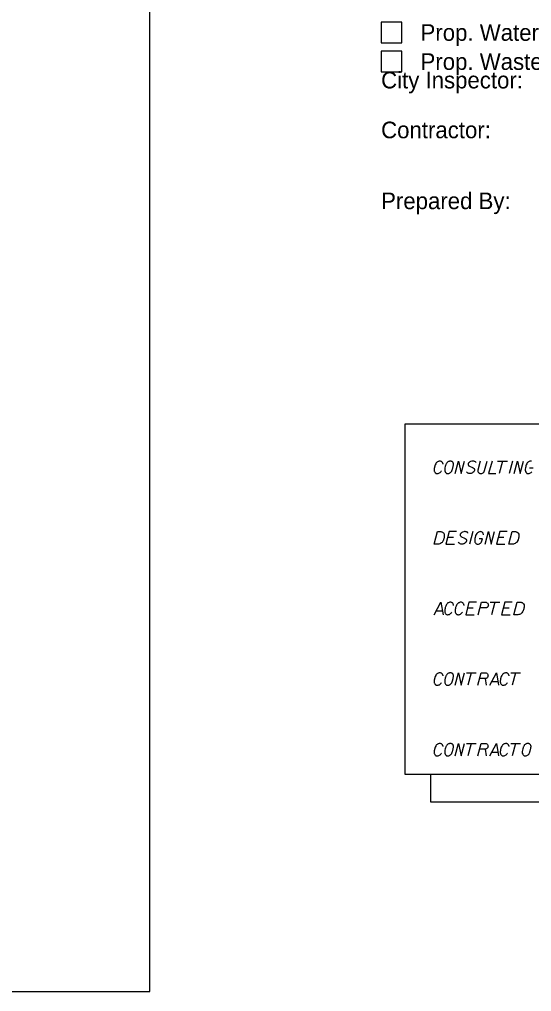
# Model space of a CAD drawing. Extents: x -2178 to -1318, y -1569 to -1077.
# Drawn here: x -1473.9 to -1412.2, y -1562.4 to -1445.4 of the extents above; entities that cross this region are included whole.
import ezdxf

# ---------------------------------------------------------------- set-up
doc = ezdxf.new("R2010")
doc.units = 0
for name, color, linetype in [('G_BORDER', 7, 'Continuous'), ('G_SHEET_EDGE', 7, 'Continuous'), ('G_SIGNATURE BLOCK', 7, 'Continuous')]:
    doc.layers.add(name, color=color, linetype=linetype)

msp = doc.modelspace()

# ---------------------------------------------------------------- linework, layer by layer
at = {"layer": 'G_BORDER'}
for points in [[(-1427.4, -1494.09), (-1321.4, -1494.09), (-1321.4, -1536.31), (-1427.4, -1536.31)], [(-1427.4, -1494.09), (-1321.4, -1494.09), (-1321.4, -1536.31), (-1427.4, -1536.31)], [(-1318.34, -1496.91), (-1321.4, -1496.91), (-1321.4, -1536.31), (-1424.34, -1536.31), (-1424.34, -1539.6), (-1318.34, -1539.6)]]:
    msp.add_lwpolyline(points, close=True, dxfattribs=at)
for points in [[(-1422.84, -1498.94), (-1422.84, -1498.9), (-1422.85, -1498.86), (-1422.86, -1498.81), (-1422.89, -1498.76), (-1422.9, -1498.74), (-1422.93, -1498.69), (-1422.97, -1498.65), (-1423.02, -1498.62), (-1423.06, -1498.6), (-1423.13, -1498.57), (-1423.19, -1498.56), (-1423.22, -1498.56), (-1423.29, -1498.57), (-1423.37, -1498.6), (-1423.43, -1498.62), (-1423.5, -1498.65), (-1423.56, -1498.69), (-1423.62, -1498.74), (-1423.65, -1498.78), (-1423.69, -1498.84), (-1423.72, -1498.9), (-1423.78, -1499.02), (-1423.82, -1499.13), (-1423.84, -1499.21), (-1423.85, -1499.26), (-1423.87, -1499.32), (-1423.89, -1499.45), (-1423.9, -1499.54), (-1423.9, -1499.65), (-1423.89, -1499.76), (-1423.87, -1499.82), (-1423.83, -1499.88), (-1423.81, -1499.92), (-1423.76, -1499.98), (-1423.69, -1500.04), (-1423.64, -1500.05), (-1423.57, -1500.06), (-1423.52, -1500.06), (-1423.51, -1500.06), (-1423.43, -1500.05), (-1423.34, -1500.02), (-1423.28, -1499.99), (-1423.19, -1499.93), (-1423.12, -1499.86), (-1423.06, -1499.79), (-1423.04, -1499.74)], [(-1421.93, -1498.56), (-1421.95, -1498.56), (-1422.02, -1498.57), (-1422.07, -1498.58), (-1422.11, -1498.6), (-1422.17, -1498.62), (-1422.24, -1498.65), (-1422.3, -1498.69), (-1422.35, -1498.74), (-1422.39, -1498.78), (-1422.43, -1498.84), (-1422.46, -1498.9), (-1422.5, -1498.97), (-1422.52, -1499.02), (-1422.54, -1499.09), (-1422.58, -1499.21), (-1422.61, -1499.39), (-1422.64, -1499.53), (-1422.64, -1499.66), (-1422.63, -1499.75), (-1422.58, -1499.86), (-1422.54, -1499.92), (-1422.48, -1499.99), (-1422.41, -1500.04), (-1422.38, -1500.05), (-1422.31, -1500.06), (-1422.25, -1500.06), (-1422.15, -1500.05), (-1422.07, -1500.02), (-1422.01, -1499.99), (-1421.93, -1499.93), (-1421.89, -1499.89), (-1421.85, -1499.85), (-1421.81, -1499.8), (-1421.79, -1499.76), (-1421.76, -1499.71), (-1421.75, -1499.68), (-1421.73, -1499.62), (-1421.71, -1499.55), (-1421.68, -1499.48), (-1421.67, -1499.43), (-1421.66, -1499.4), (-1421.65, -1499.35), (-1421.62, -1499.25), (-1421.61, -1499.19), (-1421.6, -1499.13), (-1421.59, -1499.04), (-1421.58, -1498.94), (-1421.58, -1498.9), (-1421.59, -1498.86), (-1421.6, -1498.81), (-1421.63, -1498.74), (-1421.67, -1498.69), (-1421.71, -1498.65), (-1421.75, -1498.62), (-1421.8, -1498.6), (-1421.84, -1498.58), (-1421.87, -1498.57), (-1421.93, -1498.56)], [(-1421.37, -1500.06), (-1420.97, -1498.56), (-1420.64, -1500.06), (-1420.24, -1498.56)], [(-1418.86, -1498.74), (-1418.88, -1498.69), (-1418.94, -1498.64), (-1418.99, -1498.62), (-1419.05, -1498.6), (-1419.13, -1498.57), (-1419.23, -1498.56), (-1419.28, -1498.56), (-1419.38, -1498.57), (-1419.53, -1498.63), (-1419.61, -1498.67), (-1419.7, -1498.73), (-1419.76, -1498.77), (-1419.78, -1498.81), (-1419.8, -1498.87), (-1419.82, -1498.91), (-1419.82, -1498.96), (-1419.8, -1499.02), (-1419.78, -1499.07), (-1419.75, -1499.12), (-1419.73, -1499.13), (-1419.2, -1499.38), (-1419.1, -1499.47), (-1419.07, -1499.51), (-1419.06, -1499.53), (-1419.04, -1499.61), (-1419.04, -1499.66), (-1419.05, -1499.71), (-1419.07, -1499.76), (-1419.12, -1499.85), (-1419.24, -1499.94), (-1419.27, -1499.97), (-1419.37, -1500.01), (-1419.43, -1500.04), (-1419.49, -1500.05), (-1419.58, -1500.06), (-1419.61, -1500.06), (-1419.73, -1500.05), (-1419.8, -1500.02), (-1419.86, -1500), (-1419.95, -1499.95), (-1420.03, -1499.87)], [(-1418.36, -1498.56), (-1418.66, -1499.65), (-1418.66, -1499.75), (-1418.63, -1499.82), (-1418.59, -1499.89), (-1418.52, -1499.97), (-1418.47, -1500), (-1418.45, -1500.01), (-1418.4, -1500.04), (-1418.27, -1500.06), (-1418.23, -1500.06), (-1418.17, -1500.05), (-1418.09, -1500.02), (-1418.01, -1499.98), (-1417.94, -1499.89), (-1417.9, -1499.85), (-1417.88, -1499.8), (-1417.84, -1499.69), (-1417.54, -1498.56)], [(-1416.93, -1498.56), (-1417.34, -1500.06), (-1416.46, -1500.06)], [(-1416.26, -1498.56), (-1415.08, -1498.56)], [(-1415.67, -1498.56), (-1416.07, -1500.06)], [(-1414.48, -1498.56), (-1414.88, -1500.06)], [(-1414.28, -1500.06), (-1413.88, -1498.56), (-1413.54, -1500.06), (-1413.14, -1498.56)], [(-1412.16, -1498.57), (-1412.22, -1498.56), (-1412.25, -1498.56), (-1412.32, -1498.57), (-1412.36, -1498.58), (-1412.46, -1498.62), (-1412.53, -1498.65), (-1412.59, -1498.69), (-1412.65, -1498.74), (-1412.68, -1498.78), (-1412.75, -1498.9), (-1412.81, -1499.02), (-1412.85, -1499.13), (-1412.87, -1499.21), (-1412.88, -1499.26), (-1412.91, -1499.38), (-1412.93, -1499.54), (-1412.93, -1499.66), (-1412.92, -1499.76), (-1412.9, -1499.82), (-1412.84, -1499.92), (-1412.79, -1499.98), (-1412.72, -1500.04), (-1412.67, -1500.05), (-1412.6, -1500.06), (-1412.54, -1500.06), (-1412.46, -1500.05), (-1412.36, -1500.02), (-1412.3, -1499.99), (-1412.22, -1499.93), (-1412.15, -1499.86)], [(-1411.97, -1499.42), (-1412.4, -1499.42)], [(-1423.5, -1507.06), (-1423.1, -1507.06), (-1423.02, -1507.07), (-1422.98, -1507.08), (-1422.92, -1507.11), (-1422.89, -1507.13), (-1422.85, -1507.15), (-1422.79, -1507.21), (-1422.76, -1507.26), (-1422.7, -1507.38), (-1422.7, -1507.64), (-1422.71, -1507.76), (-1422.72, -1507.82), (-1422.73, -1507.88), (-1422.74, -1507.93), (-1422.77, -1507.99), (-1422.79, -1508.06), (-1422.84, -1508.17), (-1422.86, -1508.22), (-1422.96, -1508.35), (-1423.04, -1508.42), (-1423.13, -1508.48), (-1423.24, -1508.52), (-1423.34, -1508.55), (-1423.44, -1508.56), (-1423.9, -1508.56), (-1423.5, -1507.06)], [(-1421.2, -1507.06), (-1422.1, -1507.06), (-1422.5, -1508.56), (-1421.46, -1508.56)], [(-1419.83, -1507.24), (-1419.85, -1507.19), (-1419.91, -1507.14), (-1419.96, -1507.12), (-1420.02, -1507.1), (-1420.1, -1507.07), (-1420.19, -1507.06), (-1420.25, -1507.06), (-1420.35, -1507.07), (-1420.5, -1507.13), (-1420.58, -1507.17), (-1420.67, -1507.23), (-1420.72, -1507.27), (-1420.75, -1507.31), (-1420.77, -1507.37), (-1420.78, -1507.41), (-1420.78, -1507.46), (-1420.77, -1507.52), (-1420.75, -1507.57), (-1420.71, -1507.62), (-1420.7, -1507.63), (-1420.17, -1507.88), (-1420.06, -1507.97), (-1420.04, -1508.01), (-1420.03, -1508.03), (-1420, -1508.11), (-1420, -1508.16), (-1420.02, -1508.21), (-1420.04, -1508.26), (-1420.09, -1508.35), (-1420.21, -1508.44), (-1420.24, -1508.47), (-1420.34, -1508.51), (-1420.39, -1508.54), (-1420.45, -1508.55), (-1420.55, -1508.56), (-1420.58, -1508.56), (-1420.7, -1508.55), (-1420.77, -1508.52), (-1420.83, -1508.5), (-1420.91, -1508.45), (-1421, -1508.37)], [(-1419.23, -1507.06), (-1419.63, -1508.56)], [(-1417.96, -1507.44), (-1417.96, -1507.4), (-1417.99, -1507.31), (-1418.02, -1507.24), (-1418.06, -1507.19), (-1418.09, -1507.15), (-1418.14, -1507.12), (-1418.19, -1507.1), (-1418.22, -1507.08), (-1418.26, -1507.07), (-1418.32, -1507.06), (-1418.34, -1507.06), (-1418.41, -1507.07), (-1418.46, -1507.08), (-1418.55, -1507.12), (-1418.62, -1507.15), (-1418.68, -1507.19), (-1418.74, -1507.24), (-1418.78, -1507.28), (-1418.85, -1507.4), (-1418.91, -1507.52), (-1418.94, -1507.63), (-1418.97, -1507.71), (-1418.98, -1507.76), (-1419, -1507.88), (-1419.02, -1508.04), (-1419.02, -1508.16), (-1419.01, -1508.26), (-1418.99, -1508.32), (-1418.93, -1508.42), (-1418.88, -1508.48), (-1418.81, -1508.54), (-1418.76, -1508.55), (-1418.69, -1508.56), (-1418.63, -1508.56), (-1418.55, -1508.55), (-1418.46, -1508.52), (-1418.4, -1508.49), (-1418.32, -1508.43), (-1418.25, -1508.36), (-1418.19, -1508.29), (-1418.07, -1507.92), (-1418.49, -1507.92)], [(-1417.76, -1508.56), (-1417.36, -1507.06), (-1417.03, -1508.56), (-1416.63, -1507.06)], [(-1415.12, -1507.06), (-1416.01, -1507.06), (-1416.41, -1508.56), (-1415.38, -1508.56)], [(-1414.51, -1507.06), (-1414.11, -1507.06), (-1414.03, -1507.07), (-1413.99, -1507.08), (-1413.93, -1507.11), (-1413.9, -1507.13), (-1413.86, -1507.15), (-1413.8, -1507.21), (-1413.77, -1507.26), (-1413.71, -1507.38), (-1413.71, -1507.64), (-1413.72, -1507.76), (-1413.73, -1507.82), (-1413.75, -1507.88), (-1413.76, -1507.93), (-1413.78, -1507.99), (-1413.8, -1508.06), (-1413.85, -1508.17), (-1413.88, -1508.22), (-1413.97, -1508.35), (-1414.05, -1508.42), (-1414.15, -1508.48), (-1414.25, -1508.52), (-1414.35, -1508.55), (-1414.45, -1508.56), (-1414.91, -1508.56), (-1414.51, -1507.06)], [(-1422.27, -1507.72), (-1421.59, -1507.72)], [(-1416.19, -1507.72), (-1415.51, -1507.72)], [(-1423.9, -1517.06), (-1423.11, -1515.56), (-1422.84, -1517.06)], [(-1421.58, -1515.94), (-1421.58, -1515.9), (-1421.59, -1515.86), (-1421.6, -1515.81), (-1421.62, -1515.76), (-1421.63, -1515.74), (-1421.67, -1515.69), (-1421.71, -1515.65), (-1421.75, -1515.62), (-1421.8, -1515.6), (-1421.87, -1515.57), (-1421.93, -1515.56), (-1421.95, -1515.56), (-1422.02, -1515.57), (-1422.11, -1515.6), (-1422.17, -1515.62), (-1422.24, -1515.65), (-1422.3, -1515.69), (-1422.35, -1515.74), (-1422.39, -1515.78), (-1422.43, -1515.84), (-1422.46, -1515.9), (-1422.52, -1516.02), (-1422.56, -1516.13), (-1422.58, -1516.21), (-1422.59, -1516.26), (-1422.6, -1516.32), (-1422.63, -1516.45), (-1422.64, -1516.54), (-1422.64, -1516.65), (-1422.63, -1516.76), (-1422.6, -1516.82), (-1422.57, -1516.88), (-1422.54, -1516.92), (-1422.5, -1516.98), (-1422.43, -1517.04), (-1422.38, -1517.05), (-1422.31, -1517.06), (-1422.26, -1517.06), (-1422.25, -1517.06), (-1422.17, -1517.05), (-1422.07, -1517.02), (-1422.01, -1516.99), (-1421.93, -1516.93), (-1421.86, -1516.86), (-1421.8, -1516.79), (-1421.78, -1516.74)], [(-1420.31, -1515.94), (-1420.31, -1515.9), (-1420.32, -1515.86), (-1420.34, -1515.81), (-1420.36, -1515.76), (-1420.37, -1515.74), (-1420.41, -1515.69), (-1420.44, -1515.65), (-1420.49, -1515.62), (-1420.54, -1515.6), (-1420.61, -1515.57), (-1420.67, -1515.56), (-1420.69, -1515.56), (-1420.76, -1515.57), (-1420.84, -1515.6), (-1420.9, -1515.62), (-1420.97, -1515.65), (-1421.03, -1515.69), (-1421.09, -1515.74), (-1421.13, -1515.78), (-1421.16, -1515.84), (-1421.2, -1515.9), (-1421.26, -1516.02), (-1421.29, -1516.13), (-1421.32, -1516.21), (-1421.33, -1516.26), (-1421.34, -1516.32), (-1421.36, -1516.45), (-1421.37, -1516.54), (-1421.37, -1516.65), (-1421.36, -1516.76), (-1421.34, -1516.82), (-1421.3, -1516.88), (-1421.28, -1516.92), (-1421.23, -1516.98), (-1421.16, -1517.04), (-1421.11, -1517.05), (-1421.04, -1517.06), (-1421, -1517.06), (-1420.98, -1517.06), (-1420.9, -1517.05), (-1420.81, -1517.02), (-1420.75, -1516.99), (-1420.67, -1516.93), (-1420.6, -1516.86), (-1420.54, -1516.79), (-1420.51, -1516.74)], [(-1418.81, -1515.56), (-1419.71, -1515.56), (-1420.11, -1517.06), (-1419.07, -1517.06)], [(-1418.61, -1517.06), (-1418.21, -1515.56), (-1417.7, -1515.56), (-1417.63, -1515.57), (-1417.6, -1515.58), (-1417.52, -1515.62), (-1417.48, -1515.65), (-1417.44, -1515.7), (-1417.41, -1515.76), (-1417.38, -1515.84), (-1417.37, -1515.91), (-1417.38, -1515.97), (-1417.39, -1516.02), (-1417.42, -1516.07), (-1417.44, -1516.1), (-1417.48, -1516.15), (-1417.52, -1516.19), (-1417.56, -1516.21), (-1417.62, -1516.23), (-1417.68, -1516.25), (-1418.39, -1516.25)], [(-1417.17, -1515.56), (-1415.99, -1515.56)], [(-1416.58, -1515.56), (-1416.98, -1517.06)], [(-1414.49, -1515.56), (-1415.39, -1515.56), (-1415.79, -1517.06), (-1414.75, -1517.06)], [(-1413.89, -1515.56), (-1413.49, -1515.56), (-1413.4, -1515.57), (-1413.37, -1515.58), (-1413.31, -1515.61), (-1413.27, -1515.63), (-1413.24, -1515.65), (-1413.18, -1515.71), (-1413.14, -1515.76), (-1413.08, -1515.88), (-1413.08, -1516.14), (-1413.1, -1516.26), (-1413.11, -1516.32), (-1413.12, -1516.38), (-1413.13, -1516.43), (-1413.15, -1516.49), (-1413.18, -1516.56), (-1413.23, -1516.67), (-1413.25, -1516.72), (-1413.34, -1516.85), (-1413.43, -1516.92), (-1413.52, -1516.98), (-1413.63, -1517.02), (-1413.72, -1517.05), (-1413.83, -1517.06), (-1414.29, -1517.06), (-1413.89, -1515.56)], [(-1423.67, -1516.61), (-1422.92, -1516.61)], [(-1419.89, -1516.22), (-1419.2, -1516.22)], [(-1415.56, -1516.22), (-1414.88, -1516.22)], [(-1422.84, -1524.44), (-1422.84, -1524.4), (-1422.85, -1524.36), (-1422.86, -1524.31), (-1422.89, -1524.26), (-1422.9, -1524.24), (-1422.93, -1524.19), (-1422.97, -1524.15), (-1423.02, -1524.12), (-1423.06, -1524.1), (-1423.13, -1524.07), (-1423.19, -1524.06), (-1423.22, -1524.06), (-1423.29, -1524.07), (-1423.37, -1524.1), (-1423.43, -1524.12), (-1423.5, -1524.15), (-1423.56, -1524.19), (-1423.62, -1524.24), (-1423.65, -1524.28), (-1423.69, -1524.34), (-1423.72, -1524.4), (-1423.78, -1524.52), (-1423.82, -1524.63), (-1423.84, -1524.71), (-1423.85, -1524.76), (-1423.87, -1524.82), (-1423.89, -1524.95), (-1423.9, -1525.04), (-1423.9, -1525.15), (-1423.89, -1525.26), (-1423.87, -1525.32), (-1423.83, -1525.38), (-1423.81, -1525.42), (-1423.76, -1525.48), (-1423.69, -1525.54), (-1423.64, -1525.55), (-1423.57, -1525.56), (-1423.52, -1525.56), (-1423.51, -1525.56), (-1423.43, -1525.55), (-1423.34, -1525.52), (-1423.28, -1525.49), (-1423.19, -1525.43), (-1423.12, -1525.36), (-1423.06, -1525.29), (-1423.04, -1525.24)], [(-1421.93, -1524.06), (-1421.95, -1524.06), (-1422.02, -1524.07), (-1422.07, -1524.08), (-1422.11, -1524.1), (-1422.17, -1524.12), (-1422.24, -1524.15), (-1422.3, -1524.19), (-1422.35, -1524.24), (-1422.39, -1524.28), (-1422.43, -1524.34), (-1422.46, -1524.4), (-1422.5, -1524.47), (-1422.52, -1524.52), (-1422.54, -1524.59), (-1422.58, -1524.71), (-1422.61, -1524.89), (-1422.64, -1525.03), (-1422.64, -1525.16), (-1422.63, -1525.25), (-1422.58, -1525.36), (-1422.54, -1525.42), (-1422.48, -1525.49), (-1422.41, -1525.54), (-1422.38, -1525.55), (-1422.31, -1525.56), (-1422.25, -1525.56), (-1422.15, -1525.55), (-1422.07, -1525.52), (-1422.01, -1525.49), (-1421.93, -1525.43), (-1421.89, -1525.39), (-1421.85, -1525.35), (-1421.81, -1525.3), (-1421.79, -1525.26), (-1421.76, -1525.21), (-1421.75, -1525.18), (-1421.73, -1525.12), (-1421.71, -1525.05), (-1421.68, -1524.98), (-1421.67, -1524.93), (-1421.66, -1524.9), (-1421.65, -1524.85), (-1421.62, -1524.75), (-1421.61, -1524.69), (-1421.6, -1524.63), (-1421.59, -1524.54), (-1421.58, -1524.44), (-1421.58, -1524.4), (-1421.59, -1524.36), (-1421.6, -1524.31), (-1421.63, -1524.24), (-1421.67, -1524.19), (-1421.71, -1524.15), (-1421.75, -1524.12), (-1421.8, -1524.1), (-1421.84, -1524.08), (-1421.87, -1524.07), (-1421.93, -1524.06)], [(-1421.37, -1525.56), (-1420.97, -1524.06), (-1420.64, -1525.56), (-1420.24, -1524.06)], [(-1420.03, -1524.06), (-1418.85, -1524.06)], [(-1419.44, -1524.06), (-1419.84, -1525.56)], [(-1418.65, -1525.56), (-1418.25, -1524.06), (-1417.74, -1524.06), (-1417.67, -1524.07), (-1417.63, -1524.08), (-1417.56, -1524.12), (-1417.51, -1524.15), (-1417.48, -1524.2), (-1417.44, -1524.26), (-1417.42, -1524.34), (-1417.41, -1524.41), (-1417.42, -1524.47), (-1417.43, -1524.52), (-1417.45, -1524.57), (-1417.48, -1524.6), (-1417.51, -1524.65), (-1417.56, -1524.69), (-1417.6, -1524.71), (-1417.65, -1524.73), (-1417.71, -1524.75), (-1418.42, -1524.75)], [(-1417.21, -1525.56), (-1416.41, -1524.06), (-1416.14, -1525.56)], [(-1414.88, -1524.44), (-1414.88, -1524.4), (-1414.89, -1524.36), (-1414.9, -1524.31), (-1414.93, -1524.26), (-1414.94, -1524.24), (-1414.97, -1524.19), (-1415.01, -1524.15), (-1415.06, -1524.12), (-1415.1, -1524.1), (-1415.17, -1524.07), (-1415.23, -1524.06), (-1415.26, -1524.06), (-1415.33, -1524.07), (-1415.41, -1524.1), (-1415.47, -1524.12), (-1415.54, -1524.15), (-1415.6, -1524.19), (-1415.66, -1524.24), (-1415.69, -1524.28), (-1415.73, -1524.34), (-1415.77, -1524.4), (-1415.82, -1524.52), (-1415.86, -1524.63), (-1415.88, -1524.71), (-1415.9, -1524.76), (-1415.91, -1524.82), (-1415.93, -1524.95), (-1415.94, -1525.04), (-1415.94, -1525.15), (-1415.93, -1525.26), (-1415.91, -1525.32), (-1415.87, -1525.38), (-1415.85, -1525.42), (-1415.8, -1525.48), (-1415.73, -1525.54), (-1415.68, -1525.55), (-1415.61, -1525.56), (-1415.56, -1525.56), (-1415.55, -1525.56), (-1415.47, -1525.55), (-1415.38, -1525.52), (-1415.32, -1525.49), (-1415.23, -1525.43), (-1415.16, -1525.36), (-1415.1, -1525.29), (-1415.08, -1525.24)], [(-1414.68, -1524.06), (-1413.5, -1524.06)], [(-1414.09, -1524.06), (-1414.49, -1525.56)], [(-1417.78, -1524.75), (-1417.63, -1525.56)], [(-1416.97, -1525.11), (-1416.23, -1525.11)], [(-1422.84, -1532.94), (-1422.84, -1532.9), (-1422.85, -1532.86), (-1422.86, -1532.81), (-1422.89, -1532.76), (-1422.9, -1532.74), (-1422.93, -1532.69), (-1422.97, -1532.65), (-1423.02, -1532.62), (-1423.06, -1532.6), (-1423.13, -1532.57), (-1423.19, -1532.56), (-1423.22, -1532.56), (-1423.29, -1532.57), (-1423.37, -1532.6), (-1423.43, -1532.62), (-1423.5, -1532.65), (-1423.56, -1532.69), (-1423.62, -1532.74), (-1423.65, -1532.78), (-1423.69, -1532.84), (-1423.72, -1532.9), (-1423.78, -1533.02), (-1423.82, -1533.13), (-1423.84, -1533.21), (-1423.85, -1533.26), (-1423.87, -1533.32), (-1423.89, -1533.45), (-1423.9, -1533.54), (-1423.9, -1533.65), (-1423.89, -1533.76), (-1423.87, -1533.82), (-1423.83, -1533.88), (-1423.81, -1533.92), (-1423.76, -1533.98), (-1423.69, -1534.04), (-1423.64, -1534.05), (-1423.57, -1534.06), (-1423.52, -1534.06), (-1423.51, -1534.06), (-1423.43, -1534.05), (-1423.34, -1534.02), (-1423.28, -1533.99), (-1423.19, -1533.93), (-1423.12, -1533.86), (-1423.06, -1533.79), (-1423.04, -1533.74)], [(-1421.93, -1532.56), (-1421.95, -1532.56), (-1422.02, -1532.57), (-1422.07, -1532.58), (-1422.11, -1532.6), (-1422.17, -1532.62), (-1422.24, -1532.65), (-1422.3, -1532.69), (-1422.35, -1532.74), (-1422.39, -1532.78), (-1422.43, -1532.84), (-1422.46, -1532.9), (-1422.5, -1532.97), (-1422.52, -1533.02), (-1422.54, -1533.09), (-1422.58, -1533.21), (-1422.61, -1533.39), (-1422.64, -1533.53), (-1422.64, -1533.66), (-1422.63, -1533.75), (-1422.58, -1533.86), (-1422.54, -1533.92), (-1422.48, -1533.99), (-1422.41, -1534.04), (-1422.38, -1534.05), (-1422.31, -1534.06), (-1422.25, -1534.06), (-1422.15, -1534.05), (-1422.07, -1534.02), (-1422.01, -1533.99), (-1421.93, -1533.93), (-1421.89, -1533.89), (-1421.85, -1533.85), (-1421.81, -1533.8), (-1421.79, -1533.76), (-1421.76, -1533.71), (-1421.75, -1533.68), (-1421.73, -1533.62), (-1421.71, -1533.55), (-1421.68, -1533.48), (-1421.67, -1533.43), (-1421.66, -1533.4), (-1421.65, -1533.35), (-1421.62, -1533.25), (-1421.61, -1533.19), (-1421.6, -1533.13), (-1421.59, -1533.04), (-1421.58, -1532.94), (-1421.58, -1532.9), (-1421.59, -1532.86), (-1421.6, -1532.81), (-1421.63, -1532.74), (-1421.67, -1532.69), (-1421.71, -1532.65), (-1421.75, -1532.62), (-1421.8, -1532.6), (-1421.84, -1532.58), (-1421.87, -1532.57), (-1421.93, -1532.56)], [(-1421.37, -1534.06), (-1420.97, -1532.56), (-1420.64, -1534.06), (-1420.24, -1532.56)], [(-1420.03, -1532.56), (-1418.85, -1532.56)], [(-1419.44, -1532.56), (-1419.84, -1534.06)], [(-1418.65, -1534.06), (-1418.25, -1532.56), (-1417.74, -1532.56), (-1417.67, -1532.57), (-1417.63, -1532.58), (-1417.56, -1532.62), (-1417.51, -1532.65), (-1417.48, -1532.7), (-1417.44, -1532.76), (-1417.42, -1532.84), (-1417.41, -1532.91), (-1417.42, -1532.97), (-1417.43, -1533.02), (-1417.45, -1533.07), (-1417.48, -1533.1), (-1417.51, -1533.15), (-1417.56, -1533.19), (-1417.6, -1533.21), (-1417.65, -1533.23), (-1417.71, -1533.25), (-1418.42, -1533.25)], [(-1417.78, -1533.25), (-1417.63, -1534.06)], [(-1417.21, -1534.06), (-1416.41, -1532.56), (-1416.14, -1534.06)], [(-1414.88, -1532.94), (-1414.88, -1532.9), (-1414.89, -1532.86), (-1414.9, -1532.81), (-1414.93, -1532.76), (-1414.94, -1532.74), (-1414.97, -1532.69), (-1415.01, -1532.65), (-1415.06, -1532.62), (-1415.1, -1532.6), (-1415.17, -1532.57), (-1415.23, -1532.56), (-1415.26, -1532.56), (-1415.33, -1532.57), (-1415.41, -1532.6), (-1415.47, -1532.62), (-1415.54, -1532.65), (-1415.6, -1532.69), (-1415.66, -1532.74), (-1415.69, -1532.78), (-1415.73, -1532.84), (-1415.77, -1532.9), (-1415.82, -1533.02), (-1415.86, -1533.13), (-1415.88, -1533.21), (-1415.9, -1533.26), (-1415.91, -1533.32), (-1415.93, -1533.45), (-1415.94, -1533.54), (-1415.94, -1533.65), (-1415.93, -1533.76), (-1415.91, -1533.82), (-1415.87, -1533.88), (-1415.85, -1533.92), (-1415.8, -1533.98), (-1415.73, -1534.04), (-1415.68, -1534.05), (-1415.61, -1534.06), (-1415.56, -1534.06), (-1415.55, -1534.06), (-1415.47, -1534.05), (-1415.38, -1534.02), (-1415.32, -1533.99), (-1415.23, -1533.93), (-1415.16, -1533.86), (-1415.1, -1533.79), (-1415.08, -1533.74)], [(-1414.68, -1532.56), (-1413.5, -1532.56)], [(-1414.09, -1532.56), (-1414.49, -1534.06)], [(-1412.59, -1532.56), (-1412.61, -1532.56), (-1412.68, -1532.57), (-1412.73, -1532.58), (-1412.77, -1532.6), (-1412.82, -1532.62), (-1412.9, -1532.65), (-1412.95, -1532.69), (-1413.01, -1532.74), (-1413.05, -1532.78), (-1413.08, -1532.84), (-1413.12, -1532.9), (-1413.16, -1532.97), (-1413.18, -1533.02), (-1413.2, -1533.09), (-1413.24, -1533.21), (-1413.27, -1533.39), (-1413.3, -1533.53), (-1413.3, -1533.66), (-1413.29, -1533.75), (-1413.24, -1533.86), (-1413.2, -1533.92), (-1413.14, -1533.99), (-1413.07, -1534.04), (-1413.04, -1534.05), (-1412.97, -1534.06), (-1412.91, -1534.06), (-1412.81, -1534.05), (-1412.73, -1534.02), (-1412.67, -1533.99), (-1412.59, -1533.93), (-1412.55, -1533.89), (-1412.51, -1533.85), (-1412.47, -1533.8), (-1412.45, -1533.76), (-1412.42, -1533.71), (-1412.41, -1533.68), (-1412.39, -1533.62), (-1412.36, -1533.55), (-1412.34, -1533.48), (-1412.33, -1533.43), (-1412.32, -1533.4), (-1412.3, -1533.35), (-1412.28, -1533.25), (-1412.27, -1533.19), (-1412.26, -1533.13), (-1412.25, -1533.04), (-1412.23, -1532.94), (-1412.23, -1532.9), (-1412.25, -1532.86), (-1412.26, -1532.81), (-1412.29, -1532.74), (-1412.33, -1532.69), (-1412.36, -1532.65), (-1412.41, -1532.62), (-1412.46, -1532.6), (-1412.49, -1532.58), (-1412.53, -1532.57), (-1412.59, -1532.56)], [(-1416.97, -1533.61), (-1416.23, -1533.61)]]:
    msp.add_lwpolyline(points, dxfattribs=at)
at = {"layer": 'G_SHEET_EDGE'}
msp.add_lwpolyline([(-2178.18, -1562.44), (-1458.18, -1562.44), (-1458.18, -1082.44), (-2178.18, -1082.44)], close=True, dxfattribs=at)
at = {"layer": 'G_SIGNATURE BLOCK'}
for points in [[(-1430.3, -1448.21), (-1427.8, -1448.21), (-1427.8, -1445.71), (-1430.3, -1445.71)], [(-1430.3, -1451.71), (-1427.8, -1451.71), (-1427.8, -1449.21), (-1430.3, -1449.21)]]:
    msp.add_lwpolyline(points, close=True, dxfattribs=at)

# ---------------------------------------------------------------- texts
for s, p in [('Prop. Water Built With Field Changes', (-1425.55, -1447.96)), ('Prop. Wastewater Built With Field Changes', (-1425.55, -1451.46)), ('City Inspector:', (-1430.3, -1453.69)), ('Contractor:', (-1430.3, -1459.69)), ('Prepared By:', (-1430.3, -1468.23))]:
    msp.add_text(s, height=2, dxfattribs=at).set_placement(p)

doc.saveas('drawing.dxf')
